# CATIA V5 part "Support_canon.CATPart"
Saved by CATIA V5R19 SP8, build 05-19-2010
Part number: Support_canon
Bounding box of the stored display mesh (mm): x -300 to 300, y -450 to 1500, z -150 to 299.807
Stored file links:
  G:\EU_thinkMotion\CFAO_2010\MMS_groupe2\MMS_groupe2\OK\mmartini\mmartiniCFAO\Support_canon.CATPart
  C:\Users\Mathieu Martini\Desktop\CFAO\Animation\CFAO.CATProduct
  G:\EU_thinkMotion\CFAO_2010\MMS_groupe2\MMS_groupe2\OK\mmartini\mmartiniCFAO\Berceau.CATPart
  G:\EU_thinkMotion\CFAO_2010\MMS_groupe2\MMS_groupe2\OK\mmartini\mmartiniCFAO\Squelette.CATPart
  G:\EU_thinkMotion\CFAO_2010\MMS_groupe2\MMS_groupe2\OK\mmartini\mmartiniCFAO\loidecommande.CATPart
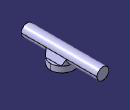
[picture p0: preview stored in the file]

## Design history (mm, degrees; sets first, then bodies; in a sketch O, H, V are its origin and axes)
External parameters (linked from other documents)
  External.diametre_canon = 150 mm
AxisSystem1: origin (0, 0, 0), X (1, 0, 0), Y (0, 1, 0), Z (0, 0, 1)
Set1
  Sketch1 on Plane1, origin (0, 0, 0), H (1, 0, 0), V (0, 1, 0)
    circle A1 centre (0, 450) radius 300
    point P1 (0, 450)
    reference projected point E1 (0, 450) from Point1
    radius A1 = 300 {= External.diametre_canon *2}
    coincidence: P1 E1
Set2
  DatumSurface1: linked copy from another document
  Plane1: linked copy from another document
  Point1 "point_axe_pivot_canon_berceau": linked copy from another document
  Plane2: linked copy from another document
  Point2 "pt_canonvertical": linked copy from another document
  Plane3 "fin_canon": linked copy from another document
  Plane4 "Plan_fin_canon": linked copy from another document
Body1 (main body)
  Pad1: profile Sketch1, direction (0, 0, 1), length -150 {= -External.diametre_canon}
  Sketch2 on Plane2, origin (0, 0, 0), H (-1, 0, 0), V (0, 0, 1)
    circle A1 centre (0, 150) radius 150
    point P1 (0, 150)
    reference projected point E1 (0, 150) from Point2
    radius A1 = 150 {= External.diametre_canon}
    coincidence: P1 E1
  Pad2: profile Sketch2, direction (0, 1, 0), up to Plane3, opposite side length -1500 {= -External.diametre_canon *10}
  Sketch3 on start face of Pad1, origin (0, 0, 0), H (1, 0, 0), V (0, 1, 0)
    projected circle E1 centre (0, 450) radius 300 from start face of Pad1
  Sketch4 on Plane2, origin (0, 0, 0), H (-1, 0, 0), V (0, 0, 1)
    line L1 (150, 150) -> (300, -150)
    point P1 (150, 150)
    point P2 (300, -150)
    line L2 (300, -150) -> (0, -150)
    point P3 (0, -150)
    point P4 (0, 150)
    line L3 (0, 150) -> (150, 150)
    axis line L4 (0, 150) -> (0, -150)
    point P5 (-150, 150)
    point P6 (0, 150)
    line L5 (0, 150) -> (-150, 150)
    point P7 (-300, -150)
    line L6 (-150, 150) -> (-300, -150)
    point P8 (0, -150)
    line L7 (-300, -150) -> (0, -150)
    reference projected point E1 (0, 150) from Point2
    length L3 = 150 {= External.diametre_canon}
    distance L3 L2 = 300 {= External.diametre_canon *2}
    length L2 = 300 {= External.diametre_canon *2}
    horizontal: L2 H, L3 H
    vertical: L4 V
    symmetry: P1 P5 L4, P4 P6 L4, L3 L5 L4, P2 P7 L4, L1 L6 L4, P3 P8 L4, L2 L7 L4
    coincidence: P4 E1, P3 P8, P4 P6
  SolidCombine1: FirstComponentProfile Sketch3, FirstComponentDirection Sketch3, SecondComponentProfile Sketch4, SecondComponentDirection Sketch4
  Sketch5 on face, origin (0, 0, 0), H (0, 1, 0), V (0, 0, 1)
    line L1 (0, 0) -> (88.4429, -10)
    point P1 (88.4429, -10)
    line L2 (88.4429, -10) -> (170.319, 0)
    point P2 (88.4429, -10)
    point P3 (170.319, 0)
    line L3 (170.319, 0) -> (2669.8824, 0)
    point P4 (170.319, 0)
    distance P1 L3 = 10
    coincidence: P2 L1, P3 H, P4 L2, P4 H
    horizontal: L3 H
  Sketch6 on face, origin (0, 0, 0), H (0, 1, 0), V (0, 0, 1)
    line L1 (0, 0) -> (88.4429, -10)
    point P1 (88.4429, -10)
    line L2 (88.4429, -10) -> (170.319, 0)
    point P2 (88.4429, -10)
    point P3 (170.319, 0)
    line L3 (170.319, 0) -> (2669.8824, 0)
    point P4 (170.319, 0)
    distance P1 L3 = 10
    coincidence: P2 L1, P3 H, P4 L2, P4 H
    horizontal: L3 H
  Sketch7 on start face of Pad2, origin (0, 1500, 0), H (-1, 0, 0), V (0, 0, 1)
    circle A1 centre (0, 150) radius 100
    point P1 (0, 150)
    reference projected point E1 (0, 150) from Point2
    radius A1 = 100 {= External.diametre_canon /2+External.diametre_canon /6}
    coincidence: P1 E1
  Pocket1: profile Sketch7, direction (0, -1, 0), through (limit type 6)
